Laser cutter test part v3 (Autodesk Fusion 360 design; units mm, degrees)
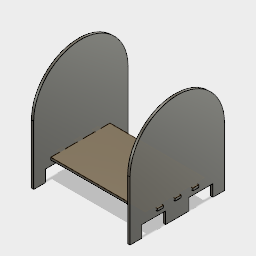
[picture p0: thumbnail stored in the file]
sketch "Sketch1" plane through (0, 0, 0) normal (0, 1, 0) x axis (1, 0, 0)
  line L1 (-80, -50) -> (80, -50)
  line L2 (-80, 50) -> (-80, -50)
  line L3 (80, 50) -> (-80, 50)
  line L4 (80, -50) -> (80, 50)
  line L5 (-80, 50) -> (80, -50)
  line L6 (80, 50) -> (-80, -50)
  point P2 (80, -50)
  point P3 (-80, -50)
  dimension "d1" distance P2 P3 = 160
  dimension "d2" distance L1 L3 = 100
extrude "Extrude1" new body sketch "Sketch1" profile of L1 L2 L3 L4 along normal blind 4
sketch "Sketch2" plane through (0, 4, 0) normal (0, 1, 0) x axis (-1, 0, 0)
  line L1 (80, -50) -> (-80, -50)
  line L2 (80, 50) -> (80, -50)
  line L3 (-80, 50) -> (80, 50)
  line L4 (-80, -50) -> (-80, 50)
  circle C1 centre (0, -50) radius 80
extrude "Extrude2" sketch "Sketch2" profile of L1 C1 blind -4
copy_paste_bodies "CopyPasteBodies1"
move "Move1"
move_face "MoveFace1"
move_face "MoveFace2"
move_face "MoveFace3"
sketch "Sketch3" plane through (0, 0, 0) normal (0, 1, 0) x axis (1, 0, 0)
  line L1 (-20, -30) -> (-60, -30)
  line L2 (-60, -50) -> (-20, -50)
  line L3 (-20, -50) -> (-20, -30)
  line L4 (-60, -30) -> (-60, -50)
  line L5 (-60, -30) -> (-20, -50)
  line L6 (-20, -30) -> (-60, -50)
  line L7 (160, -30) -> (120, -30)
  line L8 (120, -50) -> (160, -50)
  line L9 (160, -50) -> (160, -30)
  line L10 (120, -30) -> (120, -50)
  line L11 (120, -30) -> (160, -50)
  line L12 (160, -30) -> (120, -50)
  line L13 (60, -30) -> (20, -30)
  line L14 (20, -50) -> (60, -50)
  line L15 (60, -50) -> (60, -30)
  line L16 (20, -30) -> (20, -50)
  line L17 (20, -30) -> (60, -50)
  line L18 (60, -30) -> (20, -50)
  line L19 (-80, -50) -> (-80, 50)
  line L20 (80, 50) -> (80, -50)
  line L21 (80, -50) -> (-80, -50)
  line L22 (-80, -50) -> (80, -50)
  line L23 (240, -50) -> (240, -30)
  line L24 (240, -30) -> (200, -50)
  line L25 (240, -30) -> (200, -30)
  line L26 (200, -50) -> (240, -50)
  line L27 (200, -30) -> (200, -50)
  line L28 (200, -30) -> (240, -50)
  line L29 (100, -50) -> (100, 50)
  line L30 (260, -50) -> (100, -50)
  line L31 (100, -50) -> (260, -50)
  line L32 (260, 50) -> (260, -50)
  point P5 (-60, -30)
  point P6 (-20, -30)
  point P10 (120, -30)
  point P11 (160, -30)
  point P15 (20, -30)
  point P16 (60, -30)
  point P23 (200, -30)
  point P24 (240, -30)
  dimension "d11" distance P5 P6 = 40
  dimension "d12" distance L1 L2 = 20
  dimension "d13" distance P10 P11 = 40
  dimension "d14" distance L7 L8 = 20
  dimension "d15" distance P15 P16 = 40
  dimension "d16" distance L13 L14 = 20
  dimension "d17" distance L4 L19 = 20
  dimension "d18" distance L15 L20 = 20
  dimension "d21" distance P23 P24 = 40
  dimension "d22" distance L25 L26 = 20
  dimension "d24" distance L23 L32 = 20
  dimension "d25" distance L10 L29 = 20
extrude "Extrude4" sketch "Sketch3" profile of L1 L2 L3 L4 L7 L8 L9 L10 L13 L14 L15 L16 L21 L22 L23 L25 L26 L27 L30 L31 blind 4
sketch "Sketch4" plane through (0, 0, 0) normal (0, 1, 0) x axis (1, 0, 0)
  line L1 (-80.2937, -161.0513) -> (79.7063, -161.0513)
  line L2 (-80.2937, -61.0513) -> (-80.2937, -161.0513)
  line L3 (79.7063, -61.0513) -> (-80.2937, -61.0513)
  line L4 (79.7063, -161.0513) -> (79.7063, -61.0513)
  line L5 (-80.2937, -61.0513) -> (79.7063, -161.0513)
  line L6 (79.7063, -61.0513) -> (-80.2937, -161.0513)
  dimension "d28" distance L2 L4 = 160
  dimension "d29" distance L1 L3 = 100
extrude "Extrude5" sketch "Sketch4" profile of L1 L2 L3 L4 blind 4
move "Move2"
move_face "MoveFace4"
move_face "MoveFace5"
move "Move3"
move "Move4"
sketch "Sketch5" plane through (0, 0, 0) normal (0, 1, 0) x axis (1, 0, 0)
  line L1 (-83.5772, -122.4369) -> (-79.5772, -122.4369)
  line L2 (-83.5772, -112.4369) -> (-83.5772, -122.4369)
  line L3 (-79.5772, -112.4369) -> (-83.5772, -112.4369)
  line L4 (-79.5772, -122.4369) -> (-79.5772, -112.4369)
  line L5 (-83.5772, -112.4369) -> (-79.5772, -122.4369)
  line L6 (-79.5772, -112.4369) -> (-83.5772, -122.4369)
  line L7 (-79.5772, -97.4369) -> (80.4228, -97.4369)
  line L8 (-79.5772, -142.4369) -> (-83.5772, -152.4369)
  line L9 (-83.5772, -142.4369) -> (-79.5772, -152.4369)
  line L10 (-79.5772, -152.4369) -> (-79.5772, -142.4369)
  line L11 (-83.5772, -152.4369) -> (-79.5772, -152.4369)
  line L12 (-83.5772, -142.4369) -> (-83.5772, -152.4369)
  line L13 (-79.5772, -142.4369) -> (-83.5772, -142.4369)
  line L14 (-79.5772, -172.4369) -> (-83.5772, -182.4369)
  line L15 (-83.5772, -172.4369) -> (-79.5772, -182.4369)
  line L16 (-79.5772, -182.4369) -> (-79.5772, -172.4369)
  line L17 (-83.5772, -182.4369) -> (-79.5772, -182.4369)
  line L18 (-83.5772, -172.4369) -> (-83.5772, -182.4369)
  line L19 (-79.5772, -172.4369) -> (-83.5772, -172.4369)
  line L20 (84.4228, -142.4369) -> (80.4228, -152.4369)
  line L21 (84.4228, -182.4369) -> (84.4228, -172.4369)
  line L22 (80.4228, -142.4369) -> (84.4228, -152.4369)
  line L23 (80.4228, -172.4369) -> (80.4228, -182.4369)
  line L24 (80.4228, -182.4369) -> (84.4228, -182.4369)
  line L25 (84.4228, -172.4369) -> (80.4228, -182.4369)
  line L26 (80.4228, -152.4369) -> (84.4228, -152.4369)
  line L27 (84.4228, -142.4369) -> (80.4228, -142.4369)
  line L28 (84.4228, -112.4369) -> (80.4228, -112.4369)
  line L29 (84.4228, -122.4369) -> (84.4228, -112.4369)
  line L30 (80.4228, -122.4369) -> (84.4228, -122.4369)
  line L31 (80.4228, -112.4369) -> (80.4228, -122.4369)
  line L32 (80.4228, -142.4369) -> (80.4228, -152.4369)
  line L33 (80.4228, -172.4369) -> (84.4228, -182.4369)
  line L34 (84.4228, -172.4369) -> (80.4228, -172.4369)
  line L35 (84.4228, -112.4369) -> (80.4228, -122.4369)
  line L36 (84.4228, -152.4369) -> (84.4228, -142.4369)
  line L37 (80.4228, -112.4369) -> (84.4228, -122.4369)
  line L38 (-79.5772, -197.4369) -> (-79.5772, -97.4369)
  line L39 (-79.5772, -97.4369) -> (-79.5772, -197.4369)
  line L40 (80.4228, -197.4369) -> (-79.5772, -197.4369)
  line L41 (80.4228, -97.4369) -> (80.4228, -197.4369)
  line L42 (80.4228, -197.4369) -> (80.4228, -97.4369)
  point P4 (-83.5772, -112.4369)
  point P5 (-79.5772, -112.4369)
  point P2 (-79.5772, -122.4369)
  point P10 (-83.5772, -142.4369)
  point P13 (-79.5772, -142.4369)
  point P12 (-79.5772, -152.4369)
  point P15 (-83.5772, -172.4369)
  point P18 (-79.5772, -172.4369)
  point P17 (-79.5772, -182.4369)
  point P20 (80.4228, -112.4369)
  point P23 (84.4228, -112.4369)
  point P22 (84.4228, -122.4369)
  point P26 (84.4228, -142.4369)
  point P27 (80.4228, -142.4369)
  point P24 (84.4228, -152.4369)
  point P31 (84.4228, -172.4369)
  point P33 (80.4228, -172.4369)
  point P30 (84.4228, -182.4369)
  point P32 (80.4228, -182.4369)
  dimension "d16" = 20
  dimension "d32" distance P4 P5 = 4
  dimension "d33" distance P2 P5 = 10
  dimension "d34" distance L3 L7 = 15
  dimension "d35" distance P10 P13 = 4
  dimension "d36" distance P12 P13 = 10
  dimension "d37" distance P15 P18 = 4
  dimension "d38" distance P17 P18 = 10
  dimension "d39" distance L1 L13 = 20
  dimension "d40" distance L11 L19 = 20
  dimension "d41" distance P20 P23 = 4
  dimension "d42" distance P22 P23 = 10
  dimension "d43" distance P26 P27 = 4
  dimension "d44" distance P24 P26 = 10
  dimension "d45" distance P31 P33 = 4
  dimension "d46" distance P30 P31 = 10
  dimension "d47" distance L27 L30 = 20
  dimension "d48" distance L26 L34 = 20
  dimension "d51" distance P32 L40 = 15
extrude "Extrude6" sketch "Sketch5" profile of L1 L2 L3 L4 L10 L11 L12 L13 L16 L17 L18 L19 blind 4
extrude "Extrude7" sketch "Sketch5" profile of L21 L23 L24 L26 L27 L28 L29 L30 L31 L32 L34 L36 blind 4
align "Align1"
align "Align2"
move "Move5"
combine "Combine1"
align "Align3"
align "Align4"
move "Move6"
move "Move7"
move "Move8"
move "Move9"
move "Move10"
move "Move11"
move_face "MoveFace6"
move "Move12"
move "Move13"
move "Move14"
sketch "Sketch6" plane through (84.4228, 0, 0) normal (1, 0, 0) x axis (0, 0, -1)
  line L1 (20, 24) -> (20, 44)
  line L2 (60, 24) -> (20, 24)
  line L3 (60, 44) -> (60, 24)
  line L4 (100, 44) -> (60, 44)
  line L5 (100, 24) -> (100, 44)
  line L6 (120, 24) -> (100, 24)
  line L7 (120, 124) -> (120, 24)
  line L8 (-40, 24) -> (-40, 124)
  line L9 (-20, 24) -> (-40, 24)
  line L10 (-20, 44) -> (-20, 24)
  line L11 (20, 44) -> (-20, 44)
  line L12 (20, 44) -> (20, 24)
  line L13 (-20, 44) -> (20, 44)
  line L14 (-20, 24) -> (-20, 44)
  line L15 (-40, 24) -> (-20, 24)
  line L16 (-40, 124) -> (-40, 24)
  line L17 (120, 24) -> (120, 124)
  line L18 (100, 24) -> (120, 24)
  line L19 (100, 44) -> (100, 24)
  line L20 (60, 44) -> (100, 44)
  line L21 (60, 24) -> (60, 44)
  line L22 (20, 24) -> (60, 24)
  line L23 (14.3563, 52.4329) -> (4.3563, 52.4329)
  line L24 (14.3563, 56.4329) -> (14.3563, 52.4329)
  line L25 (4.3563, 56.4329) -> (14.3563, 56.4329)
  line L26 (4.3563, 52.4329) -> (4.3563, 56.4329)
  line L27 (44.3563, 52.4329) -> (34.3563, 52.4329)
  line L28 (44.3563, 56.4329) -> (44.3563, 52.4329)
  line L29 (34.3563, 56.4329) -> (44.3563, 56.4329)
  line L30 (34.3563, 52.4329) -> (34.3563, 56.4329)
  line L31 (74.3563, 52.4329) -> (64.3563, 52.4329)
  line L32 (74.3563, 56.4329) -> (74.3563, 52.4329)
  line L33 (64.3563, 56.4329) -> (74.3563, 56.4329)
  line L34 (64.3563, 52.4329) -> (64.3563, 56.4329)
  curve K1 (91.6385, 152.014) -> (-4.3694, 151.9441)
  curve K2 (91.6283, 165.995) -> (91.6385, 152.014)
  curve K3 (-4.3796, 165.9251) -> (91.6283, 165.995)
  curve K4 (-4.3694, 151.9441) -> (-4.3796, 165.9251)
  line L35 (14.3563, 56.4329) -> (4.3563, 56.4329)
  line L36 (34.3563, 56.4329) -> (14.3563, 56.4329)
  line L37 (44.3563, 56.4329) -> (34.3563, 56.4329)
  line L38 (64.3563, 56.4329) -> (44.3563, 56.4329)
  line L39 (74.3563, 56.4329) -> (64.3563, 56.4329)
  line L40 (89.3563, 56.4329) -> (74.3563, 56.4329)
  line L41 (74.3563, 56.4329) -> (89.3563, 56.4329)
  line L42 (64.3563, 56.4329) -> (74.3563, 56.4329)
  line L43 (44.3563, 56.4329) -> (64.3563, 56.4329)
  line L44 (34.3563, 56.4329) -> (44.3563, 56.4329)
  line L45 (14.3563, 56.4329) -> (34.3563, 56.4329)
  line L46 (4.3563, 56.4329) -> (14.3563, 56.4329)
  line L47 (-10.6437, 56.4329) -> (4.3563, 56.4329)
  line L48 (4.3563, 56.4329) -> (-10.6437, 56.4329)
  line L49 (4.3563, 52.4329) -> (14.3563, 52.4329)
  line L50 (-10.6437, 52.4329) -> (4.3563, 52.4329)
  line L51 (4.3563, 52.4329) -> (-10.6437, 52.4329)
  line L52 (14.3563, 52.4329) -> (4.3563, 52.4329)
  line L53 (34.3563, 52.4329) -> (14.3563, 52.4329)
  line L54 (44.3563, 52.4329) -> (34.3563, 52.4329)
  line L55 (64.3563, 52.4329) -> (44.3563, 52.4329)
  line L56 (74.3563, 52.4329) -> (64.3563, 52.4329)
  line L57 (89.3563, 52.4329) -> (74.3563, 52.4329)
  line L58 (74.3563, 52.4329) -> (89.3563, 52.4329)
  line L59 (64.3563, 52.4329) -> (74.3563, 52.4329)
  line L60 (44.3563, 52.4329) -> (64.3563, 52.4329)
  line L61 (34.3563, 52.4329) -> (44.3563, 52.4329)
  line L62 (14.3563, 52.4329) -> (34.3563, 52.4329)
  line L63 (-20, 44) -> (-20, 24)
  line L64 (20, 44) -> (-20, 44)
  line L65 (20, 24) -> (20, 44)
  line L66 (60, 24) -> (20, 24)
  line L67 (60, 44) -> (60, 24)
  line L68 (100, 44) -> (60, 44)
  line L69 (100, 24) -> (100, 44)
  line L70 (120, 24) -> (100, 24)
  line L71 (120, 124) -> (120, 24)
  line L72 (-40, 24) -> (-40, 124)
  line L73 (-20, 24) -> (-40, 24)
  arc A1 centre (40, 124) radius 80 clockwise from (-40, 124) to (120, 124)
  arc A2 centre (40, 124) radius 80 clockwise from (-40, 124) to (120, 124)
  arc A3 centre (40, 124) radius 80 clockwise from (-40, 124) to (120, 124)
sketch "Sketch7" plane through (0, 56.4329, 0) normal (0, 1, 0) x axis (-1, 0, 0)
  line L1 (-85.0034, -4.3563) -> (-81.0034, -4.3563)
  line L2 (-85.0034, -14.3563) -> (-85.0034, -4.3563)
  line L3 (-81.0034, -14.3563) -> (-85.0034, -14.3563)
  line L4 (-81.0034, -34.3563) -> (-81.0034, -14.3563)
  line L5 (-85.0034, -34.3563) -> (-81.0034, -34.3563)
  line L6 (-85.0034, -44.3563) -> (-85.0034, -34.3563)
  line L7 (-81.0034, -44.3563) -> (-85.0034, -44.3563)
  line L8 (-81.0034, -64.3563) -> (-81.0034, -44.3563)
  line L9 (-85.0034, -64.3563) -> (-81.0034, -64.3563)
  line L10 (-85.0034, -74.3563) -> (-85.0034, -64.3563)
  line L11 (-81.0034, -74.3563) -> (-85.0034, -74.3563)
  line L12 (-81.0034, -89.3563) -> (-81.0034, -74.3563)
  line L13 (78.9966, -89.3563) -> (-81.0034, -89.3563)
  line L14 (78.9966, -74.3563) -> (78.9966, -89.3563)
  line L15 (82.9966, -74.3563) -> (78.9966, -74.3563)
  line L16 (82.9966, -64.3563) -> (82.9966, -74.3563)
  line L17 (78.9966, -64.3563) -> (82.9966, -64.3563)
  line L18 (78.9966, -44.3563) -> (78.9966, -64.3563)
  line L19 (82.9966, -44.3563) -> (78.9966, -44.3563)
  line L20 (82.9966, -34.3563) -> (82.9966, -44.3563)
  line L21 (78.9966, -34.3563) -> (82.9966, -34.3563)
  line L22 (78.9966, -14.3563) -> (78.9966, -34.3563)
  line L23 (82.9966, -14.3563) -> (78.9966, -14.3563)
  line L24 (82.9966, -4.3563) -> (82.9966, -14.3563)
  line L25 (78.9966, -4.3563) -> (82.9966, -4.3563)
  line L26 (78.9966, 10.6437) -> (78.9966, -4.3563)
  line L27 (-81.0034, 10.6437) -> (78.9966, 10.6437)
  line L28 (-81.0034, -4.3563) -> (-81.0034, 10.6437)
  line L29 (-85.0034, -14.3563) -> (-81.0034, -14.3563)
  line L30 (-85.0034, -4.3563) -> (-85.0034, -14.3563)
  line L31 (-81.0034, -4.3563) -> (-85.0034, -4.3563)
  line L32 (-81.0034, 10.6437) -> (-81.0034, -4.3563)
  line L33 (78.9966, 10.6437) -> (-81.0034, 10.6437)
  line L34 (78.9966, -4.3563) -> (78.9966, 10.6437)
  line L35 (82.9966, -4.3563) -> (78.9966, -4.3563)
  line L36 (82.9966, -14.3563) -> (82.9966, -4.3563)
  line L37 (78.9966, -14.3563) -> (82.9966, -14.3563)
  line L38 (78.9966, -34.3563) -> (78.9966, -14.3563)
  line L39 (82.9966, -34.3563) -> (78.9966, -34.3563)
  line L40 (82.9966, -44.3563) -> (82.9966, -34.3563)
  line L41 (78.9966, -44.3563) -> (82.9966, -44.3563)
  line L42 (78.9966, -64.3563) -> (78.9966, -44.3563)
  line L43 (82.9966, -64.3563) -> (78.9966, -64.3563)
  line L44 (82.9966, -74.3563) -> (82.9966, -64.3563)
  line L45 (78.9966, -74.3563) -> (82.9966, -74.3563)
  line L46 (78.9966, -89.3563) -> (78.9966, -74.3563)
  line L47 (-81.0034, -89.3563) -> (78.9966, -89.3563)
  line L48 (-81.0034, -74.3563) -> (-81.0034, -89.3563)
  line L49 (-85.0034, -74.3563) -> (-81.0034, -74.3563)
  line L50 (-85.0034, -64.3563) -> (-85.0034, -74.3563)
  line L51 (-81.0034, -64.3563) -> (-85.0034, -64.3563)
  line L52 (-81.0034, -44.3563) -> (-81.0034, -64.3563)
  line L53 (-85.0034, -44.3563) -> (-81.0034, -44.3563)
  line L54 (-85.0034, -34.3563) -> (-85.0034, -44.3563)
  line L55 (-81.0034, -34.3563) -> (-85.0034, -34.3563)
  line L56 (-81.0034, -14.3563) -> (-81.0034, -34.3563)
  line L57 (82.5772, 40) -> (82.5772, 20)
  line L58 (82.5772, 40) -> (82.5772, -120)
  line L59 (82.5772, -100) -> (82.5772, -120)
  line L60 (82.5772, -60) -> (82.5772, -100)
  line L61 (82.5772, -20) -> (82.5772, -60)
  line L62 (82.5772, 20) -> (82.5772, -20)
sketch "Sketch8" plane through (-82.5772, 0, 0) normal (-1, 0, 0) x axis (0, 0, 1)
  line L1 (20, 24) -> (20, 44)
  line L2 (40, 24) -> (20, 24)
  line L3 (40, 124) -> (40, 24)
  line L4 (-120, 24) -> (-120, 124)
  line L5 (-100, 24) -> (-120, 24)
  line L6 (-100, 44) -> (-100, 24)
  line L7 (-60, 44) -> (-100, 44)
  line L8 (-60, 24) -> (-60, 44)
  line L9 (-20, 24) -> (-60, 24)
  line L10 (-20, 44) -> (-20, 24)
  line L11 (20, 44) -> (-20, 44)
  line L12 (20, 44) -> (20, 24)
  line L13 (-20, 44) -> (20, 44)
  line L14 (-20, 24) -> (-20, 44)
  line L15 (-60, 24) -> (-20, 24)
  line L16 (-60, 44) -> (-60, 24)
  line L17 (-100, 44) -> (-60, 44)
  line L18
  line L19 (-120, 24) -> (-100, 24)
  line L20 (-120, 124) -> (-120, 24)
  line L21 (40, 24) -> (40, 124)
  line L22 (20, 24) -> (40, 24)
  line L23 (-64.3563, 56.4329) -> (-74.3563, 56.4329)
  line L24 (-20, 44) -> (-20, 24)
  line L25 (20, 44) -> (-20, 44)
  line L26 (20, 24) -> (20, 44)
  line L27 (40, 24) -> (20, 24)
  line L28 (40, 124) -> (40, 24)
  line L29 (-120, 24) -> (-120, 124)
  line L30 (-100, 24) -> (-120, 24)
  line L31 (-100, 44) -> (-100, 24)
  line L32 (-60, 44) -> (-100, 44)
  line L33 (-60, 24) -> (-60, 44)
  line L34 (-20, 24) -> (-60, 24)
  arc A1 centre (-40, 124) radius 80 clockwise from (-120, 124) to (40, 124)
  arc A2 centre (-40, 124) radius 80 clockwise from (-120, 124) to (40, 124)
  arc A3 centre (-40, 124) radius 80 clockwise from (-120, 124) to (40, 124)
scale "Scale1" ScaleFactor 0.7
sketch "Sketch9" plane through (-79.7772, 0, 0) normal (1, 0, 0) x axis (0, 0, -1)
  line L1 (-26, 68) -> (-26, 54)
  line L2 (2, 68) -> (-26, 68)
  line L3 (2, 54) -> (2, 68)
  line L4 (30, 54) -> (2, 54)
  line L5 (30, 68) -> (30, 54)
  line L6 (58, 68) -> (30, 68)
  line L7 (58, 54) -> (58, 68)
  line L8 (72, 54) -> (58, 54)
  line L9 (72, 124) -> (72, 54)
  line L10 (-40, 54) -> (-40, 124)
  line L11 (-26, 54) -> (-40, 54)
  line L12 (-26, 54) -> (-26, 68)
  line L13 (-40, 54) -> (-26, 54)
  line L14 (-40, 124) -> (-40, 54)
  line L15 (72, 54) -> (72, 124)
  line L16 (58, 54) -> (72, 54)
  line L17
  line L18 (30, 68) -> (58, 68)
  line L19 (30, 54) -> (30, 68)
  line L20 (2, 54) -> (30, 54)
  line L21 (2, 68) -> (2, 54)
  line L22 (-26, 68) -> (2, 68)
  line L23 (33.0494, 73.9031) -> (40.0494, 73.9031)
  line L24 (33.0494, 76.7031) -> (33.0494, 73.9031)
  line L25 (40.0494, 76.7031) -> (33.0494, 76.7031)
  line L26 (40.0494, 73.9031) -> (40.0494, 76.7031)
  line L27 (12.0494, 73.9031) -> (19.0494, 73.9031)
  line L28 (12.0494, 76.7031) -> (12.0494, 73.9031)
  line L29 (19.0494, 76.7031) -> (12.0494, 76.7031)
  line L30 (19.0494, 73.9031) -> (19.0494, 76.7031)
  line L31 (-8.9506, 73.9031) -> (-1.9506, 73.9031)
  line L32 (-8.9506, 76.7031) -> (-8.9506, 73.9031)
  line L33 (-1.9506, 76.7031) -> (-8.9506, 76.7031)
  line L34 (-1.9506, 73.9031) -> (-1.9506, 76.7031)
  line L35 (-1.9506, 76.7031) -> (-8.9506, 76.7031)
  line L36 (12.0494, 76.7031) -> (-1.9506, 76.7031)
  line L37 (19.0494, 76.7031) -> (12.0494, 76.7031)
  line L38 (33.0494, 76.7031) -> (19.0494, 76.7031)
  line L39 (40.0494, 76.7031) -> (33.0494, 76.7031)
  line L40 (50.5494, 76.7031) -> (40.0494, 76.7031)
  line L41 (40.0494, 76.7031) -> (50.5494, 76.7031)
  line L42 (33.0494, 76.7031) -> (40.0494, 76.7031)
  line L43 (19.0494, 76.7031) -> (33.0494, 76.7031)
  line L44 (12.0494, 76.7031) -> (19.0494, 76.7031)
  line L45 (-1.9506, 76.7031) -> (12.0494, 76.7031)
  line L46 (-8.9506, 76.7031) -> (-1.9506, 76.7031)
  line L47 (-19.4506, 76.7031) -> (-8.9506, 76.7031)
  line L48 (-8.9506, 76.7031) -> (-19.4506, 76.7031)
  line L49 (-8.9506, 73.9031) -> (-1.9506, 73.9031)
  line L50 (-19.4506, 73.9031) -> (-8.9506, 73.9031)
  line L51 (-8.9506, 73.9031) -> (-19.4506, 73.9031)
  line L52 (-1.9506, 73.9031) -> (-8.9506, 73.9031)
  line L53 (12.0494, 73.9031) -> (-1.9506, 73.9031)
  line L54 (19.0494, 73.9031) -> (12.0494, 73.9031)
  line L55 (33.0494, 73.9031) -> (19.0494, 73.9031)
  line L56 (40.0494, 73.9031) -> (33.0494, 73.9031)
  line L57 (50.5494, 73.9031) -> (40.0494, 73.9031)
  line L58 (40.0494, 73.9031) -> (50.5494, 73.9031)
  line L59 (33.0494, 73.9031) -> (40.0494, 73.9031)
  line L60 (19.0494, 73.9031) -> (33.0494, 73.9031)
  line L61 (12.0494, 73.9031) -> (19.0494, 73.9031)
  line L62 (-1.9506, 73.9031) -> (12.0494, 73.9031)
  arc A1 centre (16, 124) radius 56 clockwise from (-40, 124) to (72, 124)
  arc A2 centre (16, 124) radius 56 clockwise from (-40, 124) to (72, 124)
sketch "Sketch10" plane through (0, 76.7031, 0) normal (0, 1, 0) x axis (-1, 0, 0)
  line L1 (-34.7292, 8.9506) -> (-31.9292, 8.9506)
  line L2 (-34.7292, 1.9506) -> (-34.7292, 8.9506)
  line L3 (-31.9292, 1.9506) -> (-34.7292, 1.9506)
  line L4 (-31.9292, -12.0494) -> (-31.9292, 1.9506)
  line L5 (-34.7292, -12.0494) -> (-31.9292, -12.0494)
  line L6 (-34.7292, -19.0494) -> (-34.7292, -12.0494)
  line L7 (-31.9292, -19.0494) -> (-34.7292, -19.0494)
  line L8 (-31.9292, -33.0494) -> (-31.9292, -19.0494)
  line L9 (-34.7292, -33.0494) -> (-31.9292, -33.0494)
  line L10 (-34.7292, -40.0494) -> (-34.7292, -33.0494)
  line L11 (-31.9292, -40.0494) -> (-34.7292, -40.0494)
  line L12 (-31.9292, -50.5494) -> (-31.9292, -40.0494)
  line L13 (80.0708, -50.5494) -> (-31.9292, -50.5494)
  line L14 (80.0708, -40.0494) -> (80.0708, -50.5494)
  line L15 (82.8708, -40.0494) -> (80.0708, -40.0494)
  line L16 (82.8708, -33.0494) -> (82.8708, -40.0494)
  line L17 (80.0708, -33.0494) -> (82.8708, -33.0494)
  line L18 (80.0708, -19.0494) -> (80.0708, -33.0494)
  line L19 (82.8708, -19.0494) -> (80.0708, -19.0494)
  line L20 (82.8708, -12.0494) -> (82.8708, -19.0494)
  line L21 (80.0708, -12.0494) -> (82.8708, -12.0494)
  line L22 (80.0708, 1.9506) -> (80.0708, -12.0494)
  line L23 (82.8708, 1.9506) -> (80.0708, 1.9506)
  line L24 (82.8708, 8.9506) -> (82.8708, 1.9506)
  line L25 (80.0708, 8.9506) -> (82.8708, 8.9506)
  line L26 (80.0708, 19.4506) -> (80.0708, 8.9506)
  line L27 (-31.9292, 19.4506) -> (80.0708, 19.4506)
  line L28 (-31.9292, 8.9506) -> (-31.9292, 19.4506)
  line L29 (-34.7292, 1.9506) -> (-31.9292, 1.9506)
  line L30 (-34.7292, 8.9506) -> (-34.7292, 1.9506)
  line L31 (-31.9292, 8.9506) -> (-34.7292, 8.9506)
  line L32 (-31.9292, 19.4506) -> (-31.9292, 8.9506)
  line L33 (80.0708, 19.4506) -> (-31.9292, 19.4506)
  line L34 (80.0708, 8.9506) -> (80.0708, 19.4506)
  line L35 (82.8708, 8.9506) -> (80.0708, 8.9506)
  line L36 (82.8708, 1.9506) -> (82.8708, 8.9506)
  line L37 (80.0708, 1.9506) -> (82.8708, 1.9506)
  line L38 (80.0708, -12.0494) -> (80.0708, 1.9506)
  line L39 (82.8708, -12.0494) -> (80.0708, -12.0494)
  line L40 (82.8708, -19.0494) -> (82.8708, -12.0494)
  line L41 (80.0708, -19.0494) -> (82.8708, -19.0494)
  line L42 (80.0708, -33.0494) -> (80.0708, -19.0494)
  line L43 (82.8708, -33.0494) -> (80.0708, -33.0494)
  line L44 (82.8708, -40.0494) -> (82.8708, -33.0494)
  line L45 (80.0708, -40.0494) -> (82.8708, -40.0494)
  line L46 (80.0708, -50.5494) -> (80.0708, -40.0494)
  line L47 (-31.9292, -50.5494) -> (80.0708, -50.5494)
  line L48 (-31.9292, -40.0494) -> (-31.9292, -50.5494)
  line L49 (-34.7292, -40.0494) -> (-31.9292, -40.0494)
  line L50 (-34.7292, -33.0494) -> (-34.7292, -40.0494)
  line L51 (-31.9292, -33.0494) -> (-34.7292, -33.0494)
  line L52 (-31.9292, -19.0494) -> (-31.9292, -33.0494)
  line L53 (-34.7292, -19.0494) -> (-31.9292, -19.0494)
  line L54 (-34.7292, -12.0494) -> (-34.7292, -19.0494)
  line L55 (-31.9292, -12.0494) -> (-34.7292, -12.0494)
  line L56 (-31.9292, 1.9506) -> (-31.9292, -12.0494)
offset_faces "OffsetFaces1" distance 1
offset_faces "OffsetFaces2" distance 1
offset_faces "OffsetFaces3" distance 1
offset_faces "OffsetFaces4" distance 1
sketch "Sketch11" plane through (0, 76.7031, 0) normal (0, 1, 0) x axis (-1, 0, 0)
  line L1 (-35.7292, 8.9506) -> (-31.9292, 8.9506)
  line L2 (-35.7292, 1.9506) -> (-35.7292, 8.9506)
  line L3 (-31.9292, 1.9506) -> (-35.7292, 1.9506)
  line L4 (-31.9292, -12.0494) -> (-31.9292, 1.9506)
  line L5 (-35.7292, -12.0494) -> (-31.9292, -12.0494)
  line L6 (-35.7292, -19.0494) -> (-35.7292, -12.0494)
  line L7 (-31.9292, -19.0494) -> (-35.7292, -19.0494)
  line L8 (-31.9292, -33.0494) -> (-31.9292, -19.0494)
  line L9 (-35.7292, -33.0494) -> (-31.9292, -33.0494)
  line L10 (-35.7292, -40.0494) -> (-35.7292, -33.0494)
  line L11 (-31.9292, -40.0494) -> (-35.7292, -40.0494)
  line L12 (-31.9292, -50.5494) -> (-31.9292, -40.0494)
  line L13 (80.0708, -50.5494) -> (-31.9292, -50.5494)
  line L14 (80.0708, -40.0494) -> (80.0708, -50.5494)
  line L15 (83.8708, -40.0494) -> (80.0708, -40.0494)
  line L16 (83.8708, -33.0494) -> (83.8708, -40.0494)
  line L17 (80.0708, -33.0494) -> (83.8708, -33.0494)
  line L18 (80.0708, -19.0494) -> (80.0708, -33.0494)
  line L19 (83.8708, -19.0494) -> (80.0708, -19.0494)
  line L20 (83.8708, -12.0494) -> (83.8708, -19.0494)
  line L21 (80.0708, -12.0494) -> (83.8708, -12.0494)
  line L22 (80.0708, 1.9506) -> (80.0708, -12.0494)
  line L23 (83.8708, 1.9506) -> (80.0708, 1.9506)
  line L24 (83.8708, 8.9506) -> (83.8708, 1.9506)
  line L25 (80.0708, 8.9506) -> (83.8708, 8.9506)
  line L26 (80.0708, 19.4506) -> (80.0708, 8.9506)
  line L27 (-31.9292, 19.4506) -> (80.0708, 19.4506)
  line L28 (-31.9292, 8.9506) -> (-31.9292, 19.4506)
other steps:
base_feature "Base Feature"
